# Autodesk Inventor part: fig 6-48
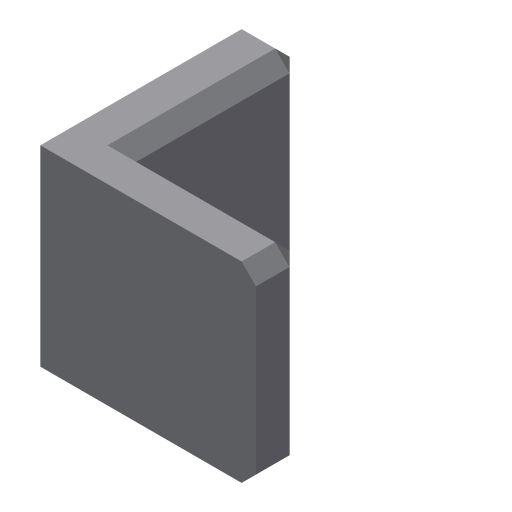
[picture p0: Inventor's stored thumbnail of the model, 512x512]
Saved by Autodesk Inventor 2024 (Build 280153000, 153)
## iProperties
Created: 2009-09
Part Number: fig 6-48
Document SubType Name: Modeling
Designer: Sham
Density: 1 g/cm^3
Material: Generic
Appearance: Default
Author: Sham
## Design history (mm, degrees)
sketch "Sketch1"
  geometry: L1 (1.789, 30)-(1.789, -5); L2 (1.789, -5)-(36.789, -5); L3 (36.789, -5)-(36.789, -15); L4 (36.789, -15)-(-8.211, -15); L5 (-8.211, -15)-(-8.211, 30); L6 (-8.211, 30)-(1.789, 30)
  constraints: 12 end point, 6 perpendicular
  dimensions: "d0" = 10 distance of L5.end L1.start; "d1" = 35 distance of L1.start L1.end; "d2" = 45 distance of L3.end L4.end; "d3" = 10 distance of L2.end L3.end (derived)
extrude "Extrusion1" new body sketch "Sketch1" distance "d4" = 40; taper "d5" = 0 deg
chamfer "Chamfer1" distance "d6" = 3; stored, may be unused: second distance "d7" = 2, angle "d8" = 45 deg
body "Solid1"
other parameters: "d1" = 35
